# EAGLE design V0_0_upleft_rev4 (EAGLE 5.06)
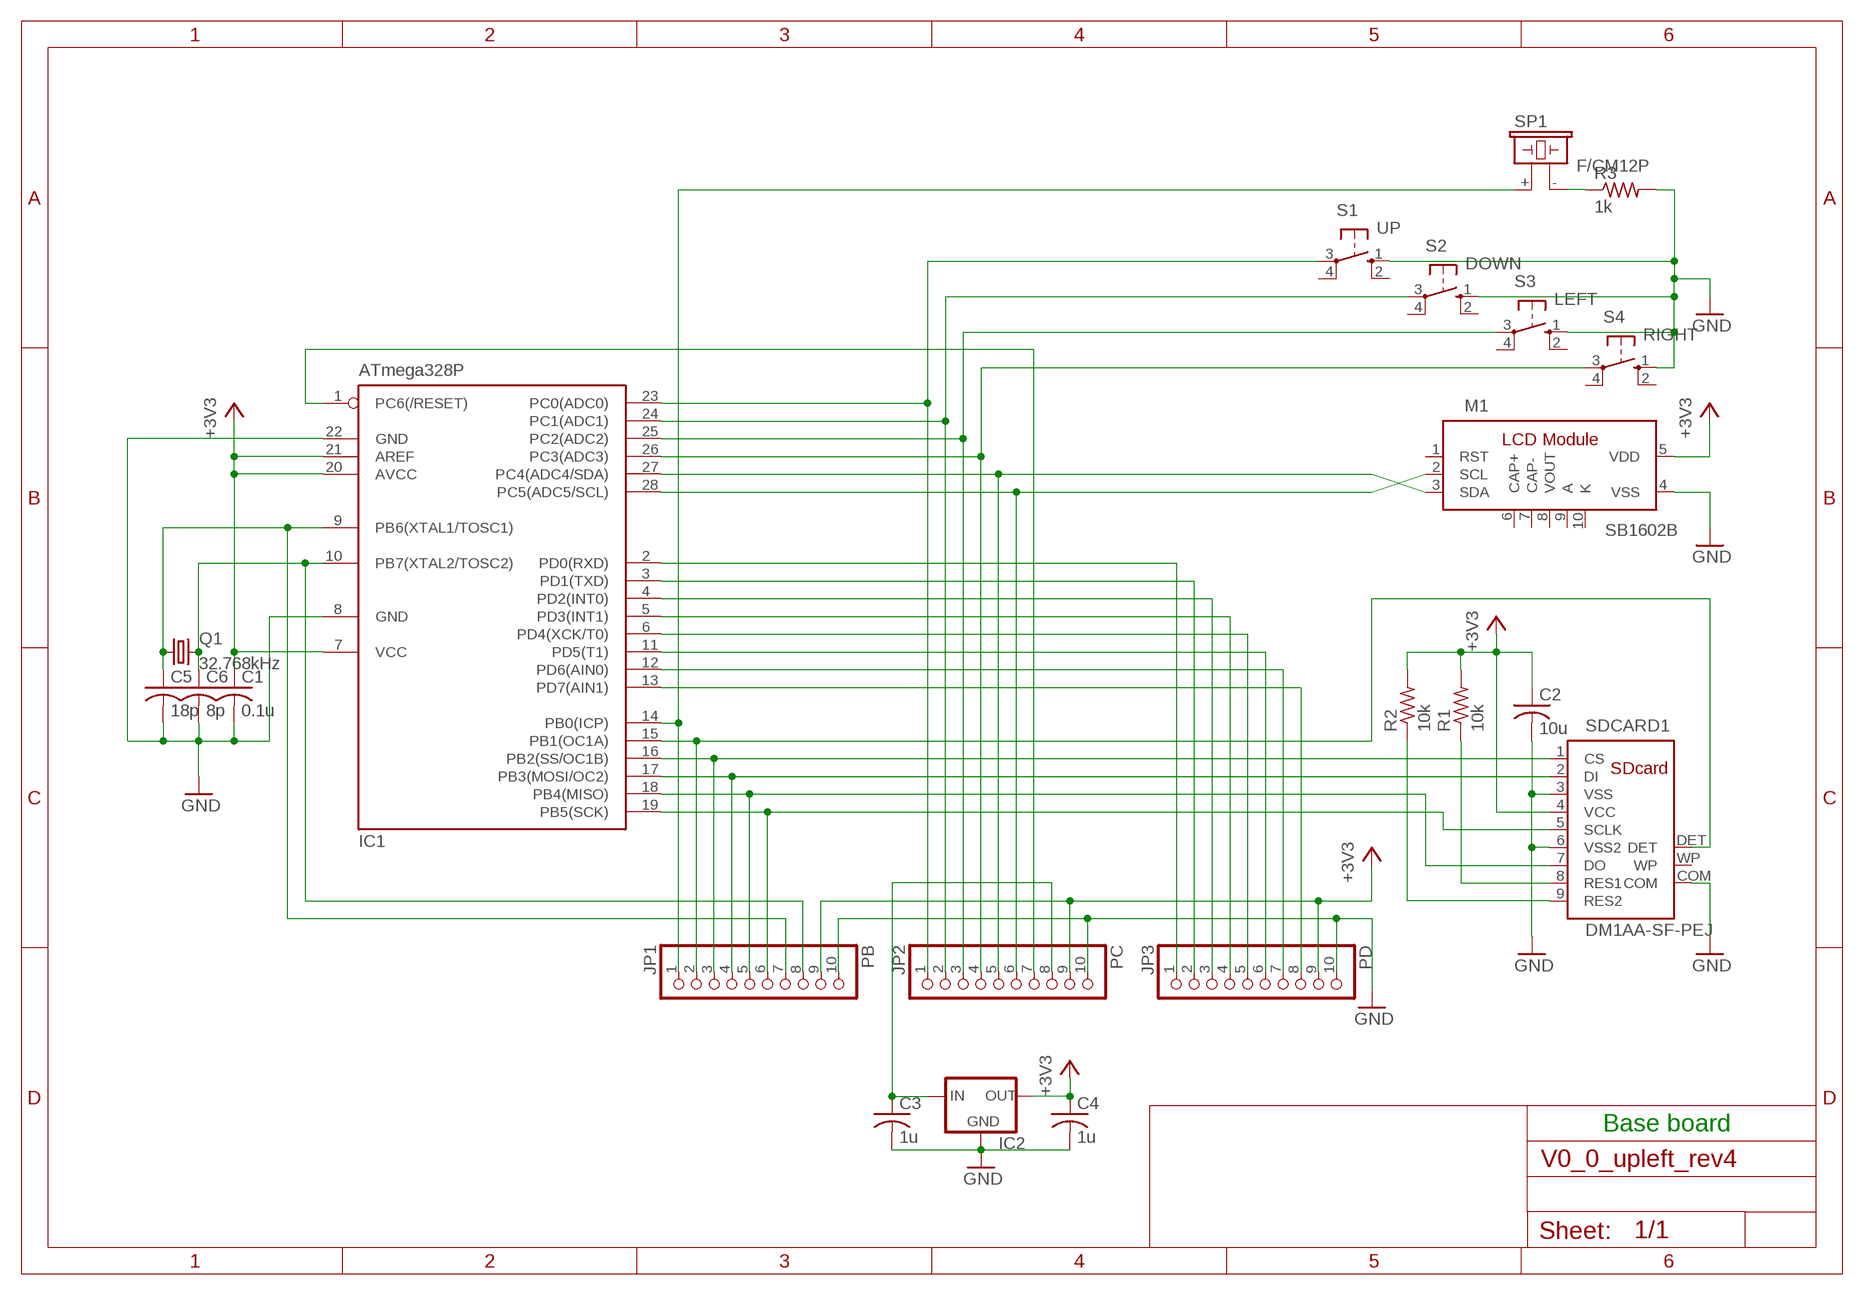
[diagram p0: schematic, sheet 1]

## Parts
C1  0.1u  C-US025-024X044  [C025-024X044]
C2  10u  C-US025-024X044  [C025-024X044]
C3  1u  C-US025-024X044  [C025-024X044]
C4  1u  C-US025-024X044  [C025-024X044]
C5  18p  C-US025-024X044  [C025-024X044]
C6  8p  C-US025-024X044  [C025-024X044]
IC1  ATmega328P  MEGA8-P  [DIL28-3]
IC2  XC63FPL  [TO92]
JP1  PB  PINHD-1X10  [1X10]
JP2  PC  PINHD-1X10  [1X10]
JP3  PD  PINHD-1X10  [1X10]
M1  SB1602B  [SB1602B]
Q1  32.768kHz  CRYSTALTC26H  [TC26H]
R1  10k  R-US_0204/5  [0204/5]
R2  10k  R-US_0204/5  [0204/5]
R3  1k  R-US_0204/5  [0204/5]
S1  UP  10-XX  [B3F-10XX]
S2  DOWN  10-XX  [B3F-10XX]
S3  LEFT  10-XX  [B3F-10XX]
S4  RIGHT  10-XX  [B3F-10XX]
SDCARD1  DM1AA-SF-PEJ  [DM1AA]
SP1  F/CM12P  [F/CM12P]

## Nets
+3V3: C1.1 C2.1 C4.1 IC1.7(VCC) IC1.20(AVCC) IC1.21(AREF) IC2.3(OUT) JP1.9 JP2.9 JP3.9 M1.5(VDD) R1.2 R2.2 SDCARD1.4(VCC)
GND: C1.2 C2.2 C3.2 C4.2 C5.2 C6.2 IC1.8(GND) IC1.22(GND) IC2.2(GND) JP1.10 JP2.10 JP3.10 M1.4(VSS) R3.2 S1.1(S) S2.1(S) S3.1(S) S4.1(S) SDCARD1.3(VSS) SDCARD1.6(VSS2) SDCARD1.COM
N$1: IC1.16(PB2(SS/OC1B)) JP1.3 SDCARD1.1(CS)
N$2: IC1.17(PB3(MOSI/OC2)) JP1.4 SDCARD1.2(DI)
N$3: IC1.18(PB4(MISO)) JP1.5 SDCARD1.7(DO)
N$4: IC1.19(PB5(SCK)) JP1.6 SDCARD1.5(SCLK)
N$5: IC1.27(PC4(ADC4/SDA)) JP2.5 M1.3(SDA)
N$6: IC1.28(PC5(ADC5/SCL)) JP2.6 M1.2(SCL)
N$7: IC1.2(PD0(RXD)) JP3.1
N$8: IC1.3(PD1(TXD)) JP3.2
N$9: R1.1 SDCARD1.8(RES1)
N$10: R2.1 SDCARD1.9(RES2)
N$11: IC1.4(PD2(INT0)) JP3.3
N$12: IC1.5(PD3(INT1)) JP3.4
N$13: IC1.6(PD4(XCK/T0)) JP3.5
N$14: IC1.11(PD5(T1)) JP3.6
N$15: IC1.12(PD6(AIN0)) JP3.7
N$16: IC1.13(PD7(AIN1)) JP3.8
N$17: R3.1 SP1.-
N$18: IC1.23(PC0(ADC0)) JP2.1 S1.3(P)
N$19: IC1.24(PC1(ADC1)) JP2.2 S2.3(P)
N$20: IC1.25(PC2(ADC2)) JP2.3 S3.3(P)
N$21: IC1.26(PC3(ADC3)) JP2.4 S4.3(P)
N$22: IC1.14(PB0(ICP)) JP1.1 SP1.+
N$23: IC1.15(PB1(OC1A)) JP1.2 SDCARD1.DET
N$24: C5.1 IC1.9(PB6(XTAL1/TOSC1)) JP1.7 Q1.1
N$26: IC1.1(PC6(/RESET)) JP2.7
N$27: C3.1 IC2.1(IN) JP2.8
N$28: C6.1 IC1.10(PB7(XTAL2/TOSC2)) JP1.8 Q1.2
Unconnected: M1.1(RST) M1.6(CAP+) M1.7(CAP-) M1.8(VOUT) S1.2(S1) S1.4(P1) S2.2(S1) S2.4(P1) S3.2(S1) S3.4(P1) S4.2(S1) S4.4(P1) SDCARD1.WP

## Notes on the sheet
- Base board

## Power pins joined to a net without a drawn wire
A: M1.9(A)
K: M1.10(K)

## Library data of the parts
C1-C6 = rcl:C-US: CAPACITOR, American symbol
IC1 = atmel:MEGA8-P: MICROCONTROLLER 8 Kbytes FLASH, 1 kbytes SRAM, 512 bytes EEPROM, USART, 4-channel 10 bit ADC, 2-channel 8 bit ADC Pin compatible with Atmega48, ATMega88, ATMega168 Source: avr.lbr
IC2 = v-reg:XC63FP: Positiv Voltage Regulators www.torex.co.jp/english/product/pro02/pdf/0201_xc62fp.pdf
JP1-JP3 = pinhead:PINHD-1X10: PIN HEADER
M1 = TOG:SB1602B: Strawberry Linux Co.,Ltd. I2C LCD Module Controler: ST7032i
Q1 = crystal:CRYSTAL: CRYSTAL
R1-R3 = rcl:R-US_: RESISTOR, American symbol
S1-S4 = switch-omron:10-XX: OMRON SWITCH
SDCARD1 = TOG:DM1AA-SF-PEJ: SDcard connector HIROSE
SP1 = buzzer:F/CM12P: BUZZER

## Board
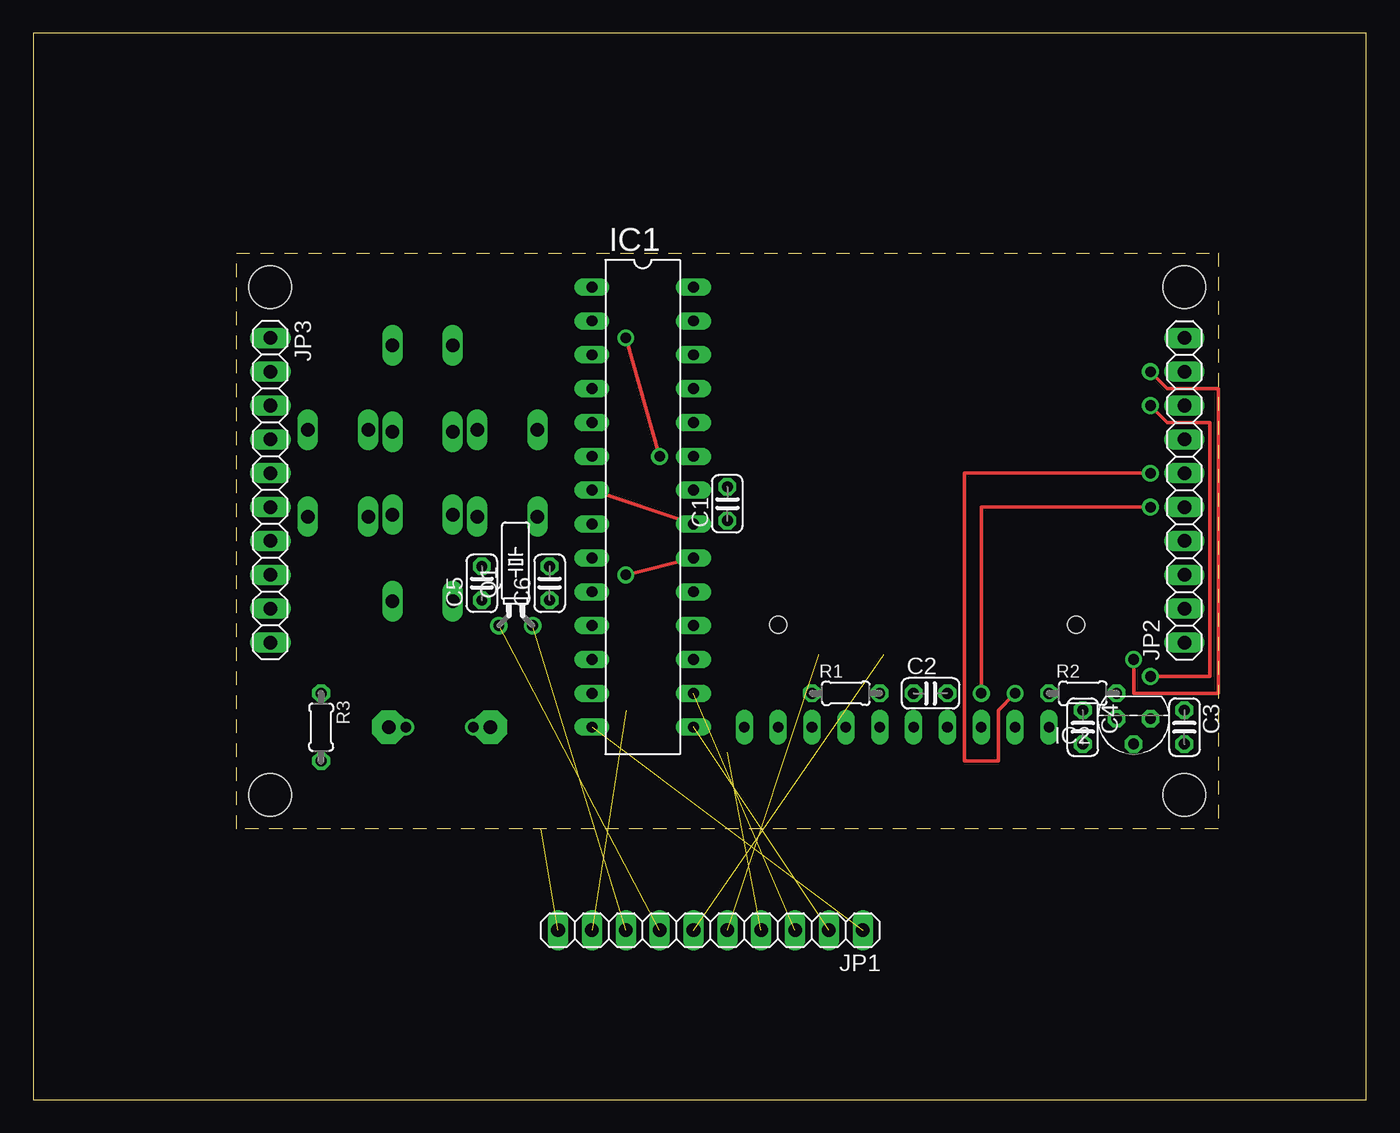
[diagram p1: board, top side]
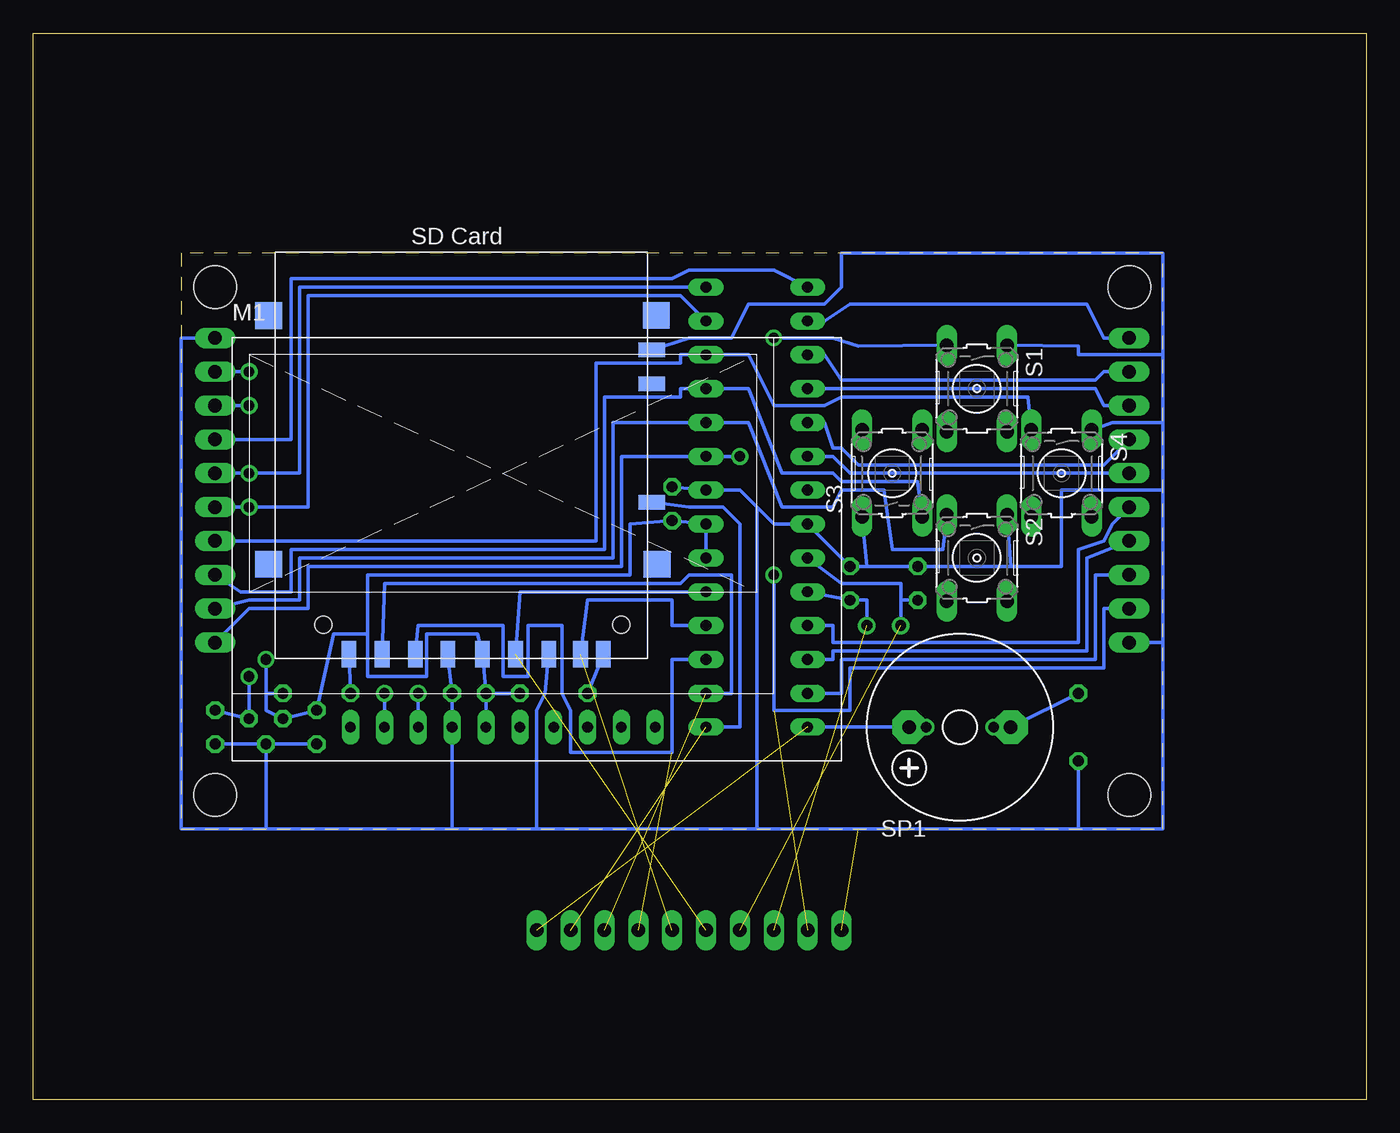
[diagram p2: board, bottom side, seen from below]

Size 100 x 80 mm. Coordinates in mm from the lower left corner, seen from the top.
Outline: 0,0 100,0 100,80 0,80 0,0
Outline: 15.24,63.5 88.9,63.5 88.9,20.32 15.24,20.32 15.24,63.5
Copper layers (1*16): Top 0.035mm / dielectric 1.5mm / Bottom 0.035mm
Design rules "default": minimum track width 10mil, minimum drill 24mil, track to track 8mil, track to pad 8mil, pad to pad 8mil, via to via 8mil, smd to smd 8mil, copper to edge 40mil, drill to drill 8mil, minimum pad ring 10mil, minimum via ring 8mil, stop-mask expansion 4mil, vias tented up to drill 0mil, thermal gap 10mil
Holes 3.2 mm at 17.78,60.96 86.36,60.96 86.36,22.86 17.78,22.86

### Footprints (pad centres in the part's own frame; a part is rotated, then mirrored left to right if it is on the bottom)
C025-024X044 = drill 0.813 octagon: 1 -1.27,0; 2 1.27,0
DIL28-3 = drill 0.813 long: 1 -16.51,-3.81; 2 -13.97,-3.81; 3 -11.43,-3.81; 4 -8.89,-3.81; 5 -6.35,-3.81; 6 -3.81,-3.81; 7 -1.27,-3.81; 8 1.27,-3.81; 9 3.81,-3.81; 10 6.35,-3.81; 11 8.89,-3.81; 12 11.43,-3.81; 13 13.97,-3.81; 14 16.51,-3.81; 15 16.51,3.81; 16 13.97,3.81; 17 11.43,3.81; 18 8.89,3.81; 19 6.35,3.81; 20 3.81,3.81; 21 1.27,3.81; 22 -1.27,3.81; 23 -3.81,3.81; 24 -6.35,3.81; 25 -8.89,3.81; 26 -11.43,3.81; 27 -13.97,3.81; 28 -16.51,3.81
TO92 = drill 0.813 octagon: 1 -1.27,0; 2 0,1.905; 3 1.27,0
1X10 = drill 1.016 long: 1 -11.43,0; 2 -8.89,0; 3 -6.35,0; 4 -3.81,0; 5 -1.27,0; 6 1.27,0; 7 3.81,0; 8 6.35,0; 9 8.89,0; 10 11.43,0
SB1602B = drill 0.8 long: 1 -13.97,-12.7; 2 -11.43,-12.7; 3 -8.89,-12.7; 4 -6.35,-12.7; 5 -3.81,-12.7; 6 -1.27,-12.7; 7 1.27,-12.7; 8 3.81,-12.7; 9 6.35,-12.7; 10 8.89,-12.7
TC26H = drill 0.813 round: 1 -1.27,0; 2 1.27,0
0204/5 = drill 0.813 octagon: 1 -2.54,0; 2 2.54,0
B3F-10XX = drill 1.016 long: 1 -3.251,2.261; 2 3.251,2.261; 3 -3.251,-2.261; 4 3.251,-2.261
DM1AA = smd 1.1 x 2: 1 3.98,14.22; 2 1.49,14.22; 3 -0.95,14.22; 4 -3.54,14.22; 5 -6.03,14.22; 6 -8.52,14.22; 7 -10.91,14.22; 8 -12.615,14.22; 9 6.47,14.22 | smd 2 x 1.1: COM -16.24,-8.62; DET -16.24,2.81; WP -16.24,-6.08 | smd 2.007 x 2.007: FG -16.64,7.455; P$13 12.5,7.455; P$14 12.5,-11.19; P$15 -16.59,-11.21 | hole 1.3: 8.39,12; -13.97,12
F/CM12P = drill 1.016 pad 2.54 octagon: + 3.81,0; - -3.81,0

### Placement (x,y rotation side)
C1  52.07,44.7 90 top
C2  67.31,30.48 0 top
C3  86.36,27.94 270 top
C4  78.74,27.94 270 top
C5  33.66,38.73 90 top
C6  38.73,38.73 90 top
IC1  45.72,44.45 270 top
IC2  82.55,28.57 180 top
JP1  50.8,12.7 180 top
JP2  86.36,45.72 90 top
JP3  17.78,45.72 270 top
M1  62.23,40.64 0 bottom
Q1  36.2,35.56 0 top
R1  60.96,30.48 0 top
R2  78.74,30.48 0 top
R3  21.59,27.94 270 top
S1  29.21,53.34 270 bottom
S2  29.21,40.64 270 bottom
S3  35.56,46.99 90 bottom
S4  22.86,46.99 270 bottom
SDCARD1  69.85,47.62 180 bottom
SP1  30.48,27.94 180 bottom

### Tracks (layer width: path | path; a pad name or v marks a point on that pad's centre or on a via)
+3V3  (via drill 0.8 pad 1.27)  (1 unrouted)
  Top 0.254: v82.55,33.02 82.55,30.48 88.9,30.48 88.9,53.34 85.09,53.34 v83.82,54.61 | v44.45,39.37 IC1.20 | IC1.21 IC1.7
  Bottom 0.254: C2.1 SDCARD1.4 66.67,34.92 70.48,34.92 70.48,31.75 74.93,31.75 74.93,34.92 | C2.1 M1.5 | IC1.20 IC1.21 C1.1 55.24,43.18 55.24,39.37 74.93,39.37 74.93,34.92 | C2.1 R1.2 | JP3.9 19.68,36.83 19.68,32.38 38.73,32.38 38.73,29.21 44.45,29.21 v44.45,39.37 | v83.82,54.61 JP2.9 | 82.55,30.48 82.55,29.21 IC2.3 C4.1 77.47,34.92 74.93,34.92 | 82.55,30.48 v82.55,33.02 | 82.55,30.48 R2.2
GND  (1 unrouted)
  Bottom 0.254: 21.59,20.32 15.24,20.32 15.24,34.29 | 21.59,20.32 38.1,20.32 45.72,20.32 | 45.72,20.32 62.23,20.32 | 62.23,20.32 68.58,20.32 | 68.58,20.32 82.55,20.32 | 82.55,20.32 88.9,20.32 88.9,57.15 JP2.10 | 15.24,34.29 15.24,45.72 | 15.24,45.72 15.24,50.8 | 15.24,50.8 15.24,55.88 | SDCARD1.3 C2.2 M1.4 68.58,20.32 | 37.47,40.01 C5.2 26.67,40.01 | 37.47,40.01 C6.2 IC1.8 44.45,43.18 45.72,44.45 | SDCARD1.6 61.59,30.48 62.23,29.21 62.23,20.32 | C1.2 IC1.22 46.99,45.72 45.72,44.45 | 15.24,34.29 JP3.10 | 21.59,20.32 R3.2 | 26.67,40.01 22.86,40.01 22.86,45.72 15.24,45.72 | 37.47,40.01 S3.1 | S4.1 19.05,50.8 15.24,50.8 | S1.1 21.59,56.52 21.59,55.88 15.24,55.88 | IC2.2 C3.2 | 26.67,40.01 S2.1 | 45.72,20.32 45.72,44.45 | SDCARD1.COM 50.8,57.15 47.62,57.15 46.35,59.69 40.64,59.69 39.37,60.96 39.37,63.5 15.24,63.5 15.24,55.88 | 82.55,20.32 IC2.2 | IC2.2 C4.2
N$1  (1 unrouted)
  Bottom 0.254: SDCARD1.1 73.66,38.73 51.44,38.73 50.8,39.37 47.62,39.37 47.62,30.48 IC1.16
N$2  (1 unrouted)
  Bottom 0.254: SDCARD1.2 71.12,35.56 64.77,35.56 64.77,31.75 62.87,31.75 62.87,35.56 60.33,35.56 60.33,30.48 59.69,29.21 59.69,26.04 52.07,26.04 52.07,33.02 IC1.17
N$3  (1 unrouted)
  Bottom 0.254: IC1.18 52.07,35.56 52.07,37.47 58.42,37.47 SDCARD1.7
N$4  (1 unrouted)
  Bottom 0.254: SDCARD1.5 63.5,38.1 IC1.19
N$5  (via drill 0.8 pad 1.27)
  Top 0.254: v71.12,30.48 71.12,44.45 v83.82,44.45
  Bottom 0.254: M1.3 v71.12,30.48 | IC1.27 51.44,60.33 79.38,60.33 79.38,44.45 v83.82,44.45 JP2.5
N$6  (via drill 0.8 pad 1.27)
  Top 0.254: v73.66,30.48 72.39,29.21 72.39,25.4 69.85,25.4 69.85,46.99 v83.82,46.99
  Bottom 0.254: IC1.28 80.01,60.96 80.01,46.99 v83.82,46.99 JP2.6 | M1.2 v73.66,30.48
N$7
  Bottom 0.254: JP3.1 19.68,57.15 20.95,59.69 38.73,59.69 40.64,58.42 IC1.2
N$8
  Bottom 0.254: IC1.3 40.64,55.88 39.37,53.98 20.32,53.98 19.68,54.61 JP3.2
N$9
  Bottom 0.254: SDCARD1.8 R1.1
N$10
  Bottom 0.254: R2.1 SDCARD1.9
N$11
  Bottom 0.254: JP3.3 19.68,52.07 20.32,53.34 IC1.4
N$12
  Bottom 0.254: IC1.5 40.64,50.8 40.01,48.9 39.37,48.9 38.1,47.62 19.68,47.62 JP3.4
N$13
  Bottom 0.254: IC1.6 40.01,48.26 38.73,46.99 JP3.5
N$14
  Bottom 0.254: IC1.11 40.01,35.56 40.01,34.29 21.59,34.29 21.59,41.27 19.68,41.91 19.05,43.18 JP3.6
N$15
  Bottom 0.254: JP3.7 20.95,40.64 20.95,33.66 40.01,33.66 40.01,33.02 IC1.12
N$16
  Bottom 0.254: IC1.13 39.37,30.48 39.37,33.02 20.32,33.02 20.32,39.37 JP3.8
N$17
  Bottom 0.254: R3.1 SP1.-
N$18  (via drill 0.8 pad 1.27)
  Top 0.254: v44.45,57.15 v46.99,48.26
  Bottom 0.254: JP2.1 83.82,36.83 79.38,36.83 79.38,40.01 55.88,40.01 55.88,48.26 IC1.23 v46.99,48.26 | v44.45,57.15 40.01,57.15 38.1,56.52 S1.3
N$19
  Bottom 0.254: JP2.2 83.82,37.47 80.01,37.47 80.01,40.64 56.52,40.64 56.52,50.8 IC1.24 46.35,50.8 43.81,44.45 40.01,44.45 39.37,45.72 36.2,45.72 35.56,41.27 31.75,41.27 S2.3
N$20
  Bottom 0.254: JP2.3 84.45,38.1 80.64,38.1 80.64,41.27 57.15,41.27 57.15,52.7 51.44,52.7 51.44,53.34 IC1.25 46.35,53.34 43.81,46.99 40.01,46.99 39.37,46.35 33.66,46.35 S3.3
N$21
  Bottom 0.254: JP2.4 57.78,41.91 57.78,55.24 51.44,55.24 51.44,55.88 IC1.26 46.35,55.88 44.45,52.07 40.64,52.07 39.37,52.7 25.4,52.7 S4.3
N$22  (1 unrouted)
  Bottom 0.254: SP1.+ IC1.14
N$23  (1 unrouted)
  Bottom 0.254: IC1.15 46.99,27.94 46.99,43.18 48.26,44.45 50.8,44.45 SDCARD1.DET
N$24  (1 unrouted)
  Bottom 0.254: IC1.9 39.37,38.73 34.92,38.73 34.92,37.47 | Q1.1 34.92,37.47 | 34.92,37.47 C5.1
N$25  (via drill 0.8 pad 1.27)
  other vias: 33.02,27.94
N$26
  Bottom 0.254: IC1.1 44.45,62.23 50.8,62.23 52.07,61.59 80.64,61.59 80.64,49.53 JP2.7
N$27  (via drill 0.8 pad 1.27)
  Top 0.254: v83.82,31.75 88.27,31.75 88.27,50.8 85.09,50.8 v83.82,52.07
  Bottom 0.254: C3.1 IC2.1 v83.82,31.75 | v83.82,52.07 JP2.8
N$28  (1 unrouted)
  Bottom 0.254: IC1.10 C6.1 37.47,37.47 Q1.2
N$29  (via drill 0.8 pad 1.27)
  other vias: 27.94,27.94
